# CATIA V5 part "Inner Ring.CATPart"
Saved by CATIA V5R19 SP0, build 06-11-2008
Part number: Inner Ring
Bounding box of the stored display mesh (mm): x -69.981 to 69.981, y 0 to 50, z -69.908 to 69.908
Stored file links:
  D:\Shriniwas\v5_r19\c16_CAT_v5r19\c16_Part\Roll curve Joint\tut_4 _final\Inner Ring.CATPart
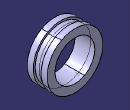
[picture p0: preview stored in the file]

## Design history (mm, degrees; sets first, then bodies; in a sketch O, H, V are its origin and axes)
Body1 (main body)
  Sketch1 on yz-plane, origin (0, 0, 0), H (0, 1, 0), V (0, 0, 1)
    point P1 (0, 50)
    line L1 (0, 50) -> (0, 70)
    line L2 (0, 70) -> (15, 70)
    line L3 (15, 70) -> (15, 65)
    line L4 (15, 65) -> (35, 65)
    line L5 (35, 65) -> (35, 70)
    point P6 (35, 70)
    line L6 (35, 70) -> (50, 70)
    line L7 (50, 70) -> (50, 50)
    line L8 (50, 50) -> (0, 50)
    distance L8 H = 50
    length L8 = 50
    length L6 = 15
    length L2 = 15
    length L7 = 20
    distance L8 L4 = 15
    coincidence: P1 V, P6 L2
    vertical: L1 V, L3 V, L5 V, L7 V
    horizontal: L2 H, L4 H, L6 H, L8 H
  Shaft1: profile Sketch1, axis Sketch1.H, angle 360
  Plane1: type Offset, Offset 10, RefPlane face of Shaft1 from Sketch1.L3, reversed
  Sketch2 on Plane1, origin (0, 25, 0), H (1, 0, 0), V (0, 0, 1)
    projected circle E1 centre (0, 0) radius 65 from edge [face of Shaft1 from Sketch1.L4 | face of Shaft1 from Sketch1.L5]
  Point1: type OnCurve, Support Sketch2, Length 192.617, RefPoint {extremum Reference Sketch2, Direction (1, 2, 3)}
